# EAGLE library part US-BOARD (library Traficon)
US-board outline Contains: 44p edge connector 3 holes for fixation of the front plate 10 leds
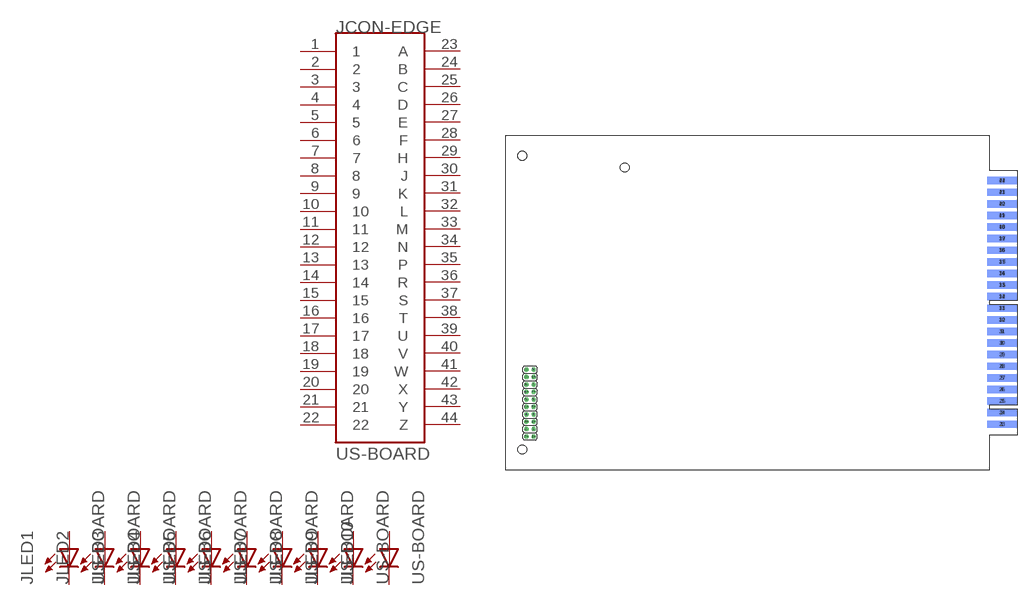
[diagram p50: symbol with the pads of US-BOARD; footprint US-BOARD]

Designator prefix J; gates CON-EDGE=CARD_EDGE_44P LED1=LED LED2=LED LED3=LED LED4=LED LED5=LED LED6=LED LED7=LED LED8=LED LED9=LED LED10=LED

## US-BOARD  [US-BOARD]
1  CON-EDGE:1
1+  LED1:A  pas
1-  LED1:C  pas
2  CON-EDGE:2
2+  LED2:A  pas
2-  LED2:C  pas
3  CON-EDGE:3
3+  LED3:A  pas
3-  LED3:C  pas
4  CON-EDGE:4
4+  LED4:A  pas
4-  LED4:C  pas
5  CON-EDGE:5
5+  LED5:A  pas
5-  LED5:C  pas
6  CON-EDGE:6
6+  LED6:A  pas
6-  LED6:C  pas
7  CON-EDGE:7
7+  LED7:A  pas
7-  LED7:C  pas
8  CON-EDGE:8
8+  LED8:A  pas
8-  LED8:C  pas
9  CON-EDGE:9
9+  LED9:A  pas
9-  LED9:C  pas
10  CON-EDGE:10
10+  LED10:A  pas
10-  LED10:C  pas
11  CON-EDGE:11
12  CON-EDGE:12
13  CON-EDGE:13
14  CON-EDGE:14
15  CON-EDGE:15
16  CON-EDGE:16
17  CON-EDGE:17
18  CON-EDGE:18
19  CON-EDGE:19
20  CON-EDGE:20
21  CON-EDGE:21
22  CON-EDGE:22
23  CON-EDGE:A
24  CON-EDGE:B
25  CON-EDGE:C
26  CON-EDGE:D
27  CON-EDGE:E
28  CON-EDGE:F
29  CON-EDGE:H
30  CON-EDGE:J
31  CON-EDGE:K
32  CON-EDGE:L
33  CON-EDGE:M
34  CON-EDGE:N
35  CON-EDGE:P
36  CON-EDGE:R
37  CON-EDGE:S
38  CON-EDGE:T
39  CON-EDGE:U
40  CON-EDGE:V
41  CON-EDGE:W
42  CON-EDGE:X
43  CON-EDGE:Y
44  CON-EDGE:Z

## Footprint US-BOARD (pad centres in mm)
smd 10.16 x 2.54: 1 169.545,15.622; 2 169.545,19.584; 3 169.545,23.547; 4 169.545,27.509; 5 169.545,31.471; 6 169.545,35.434; 7 169.545,39.396; 8 169.545,43.359; 9 169.545,47.321; 10 169.545,51.283; 11 169.545,55.246; 12 169.545,59.208; 13 169.545,63.171; 14 169.545,67.133; 15 169.545,71.096; 16 169.545,75.058; 17 169.545,79.02; 18 169.545,82.983; 19 169.545,86.945; 20 169.545,90.907; 21 169.545,94.87; 22 169.545,98.832
drill 1.016 octagon: 1+ 9.52,11.4; 1- 9.52,13.94; 2+ 6.98,11.4; 2- 6.98,13.94; 3+ 9.52,16.48; 3- 9.52,19.02; 4+ 6.98,16.48; 4- 6.98,19.02; 5+ 9.52,21.56; 5- 9.52,24.1; 6+ 6.98,21.56; 6- 6.98,24.1; 7+ 9.52,26.64; 7- 9.52,29.18; 8+ 6.98,26.64; 8- 6.98,29.18; 9+ 9.52,31.72; 9- 9.52,34.26; 10+ 6.98,31.72; 10- 6.98,34.26
smd 10.16 x 2.54 bottom: 23 169.545,15.622; 24 169.545,19.584; 25 169.545,23.547; 26 169.545,27.509; 27 169.545,31.471; 28 169.545,35.434; 29 169.545,39.396; 30 169.545,43.359; 31 169.545,47.321; 32 169.545,51.283; 33 169.545,55.246; 34 169.545,59.208; 35 169.545,63.171; 36 169.545,67.133; 37 169.545,71.096; 38 169.545,75.058; 39 169.545,79.02; 40 169.545,82.983; 41 169.545,86.945; 42 169.545,90.907; 43 169.545,94.87; 44 169.545,98.832
hole 3 at 5.57,107.36
hole 3 at 5.57,7.03
hole 3 at 40.64,103.35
